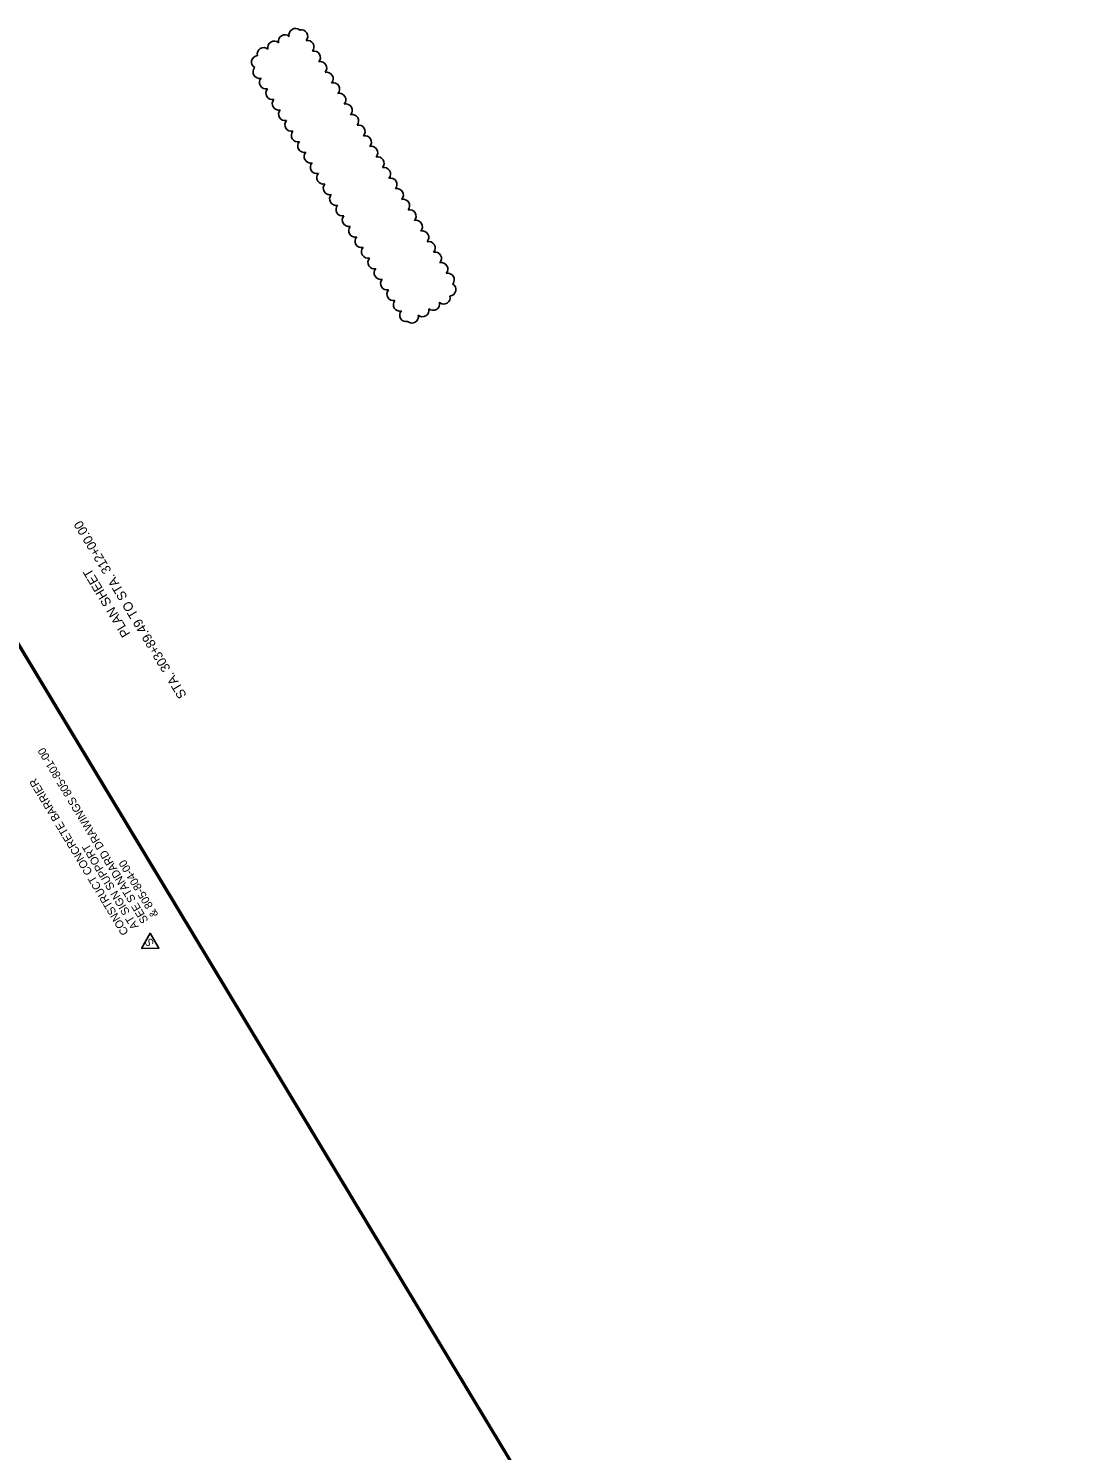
# Model space of a CAD drawing. Extents: x 1613170 to 1614989, y 1084261 to 1086549.
# Drawn here: x 1614158 to 1614953, y 1085483 to 1086549 of the extents above; entities that cross this region are included whole.
import ezdxf

# ---------------------------------------------------------------- set-up
doc = ezdxf.new("R2010")
doc.units = 0
for name, color, linetype in [('Level 17', 7, 'Continuous'), ('Level 21', 7, 'Continuous'), ('Level 4', 7, 'Continuous'), ('Level 8', 7, 'Continuous')]:
    doc.layers.add(name, color=color, linetype=linetype)

msp = doc.modelspace()

# ---------------------------------------------------------------- linework, layer by layer
at = {"layer": 'Level 17'}
msp.add_lwpolyline([(1614088.5, 1084350.8), (1613395.8, 1085500.1), (1613423.8, 1085516.9), (1613343.7, 1085653.3), (1614126.4, 1086125), (1614900.7, 1084840.3)], close=True, dxfattribs=at)
msp.add_lwpolyline([(1614088.5, 1084350.8), (1613395.8, 1085500.1), (1613423.8, 1085516.9), (1613343.7, 1085653.3), (1614126.4, 1086125), (1614900.7, 1084840.3)], close=True, dxfattribs=at)
msp.add_lwpolyline([(1614088.5, 1084350.8), (1613395.8, 1085500.1), (1613423.8, 1085516.9), (1613343.7, 1085653.3), (1614126.4, 1086125), (1614900.7, 1084840.3)], close=True, dxfattribs=at)
at = {"layer": 'Level 4'}
msp.add_lwpolyline([(1614134, 1084261.5), (1613269.4, 1085696.1), (1614088.6, 1086189.8), (1614953.2, 1084755.2)], close=True, dxfattribs=at)
at = {"layer": 'Level 8'}
msp.add_lwpolyline([(1614242.4, 1085859), (1614255.4, 1085859.3), (1614248.7, 1085870.4)], close=True, dxfattribs=at)
for centre, radius, start, end in [((1614349.8, 1086539.2), 4.86, 48.5768, 193.5768), ((1614357.7, 1086543.9), 4.86, 48.5768, 193.5768), ((1614362.1, 1086542.9), 4.86, 318.5768, 103.5768), ((1614333.9, 1086529.6), 4.86, 48.5768, 193.5768), ((1614341.8, 1086534.4), 4.86, 48.5768, 193.5768), ((1614366.8, 1086534.9), 4.86, 318.5768, 103.5768), ((1614371.6, 1086527), 4.86, 318.5768, 103.5768), ((1614329.6, 1086523.6), 4.85, 94.9006, 239.9006), ((1614376.4, 1086519.1), 4.86, 318.5768, 103.5768), ((1614330.8, 1086516.2), 4.86, 138.5768, 283.5768), ((1614335.6, 1086508.3), 4.86, 138.5768, 283.5768), ((1614381.2, 1086511.1), 4.86, 318.5768, 103.5768), ((1614340.4, 1086500.3), 4.86, 138.5768, 283.5768), ((1614386, 1086503.2), 4.86, 318.5768, 103.5768), ((1614390.7, 1086495.3), 4.86, 318.5768, 103.5768), ((1614345.2, 1086492.4), 4.86, 138.5768, 283.5768), ((1614349.9, 1086484.5), 4.86, 138.5768, 283.5768), ((1614395.5, 1086487.3), 4.86, 318.5768, 103.5768), ((1614354.7, 1086476.5), 4.86, 138.5768, 283.5768), ((1614400.3, 1086479.4), 4.86, 318.5768, 103.5768), ((1614359.5, 1086468.6), 4.86, 138.5768, 283.5768), ((1614405.1, 1086471.5), 4.86, 318.5768, 103.5768), ((1614409.9, 1086463.5), 4.86, 318.5768, 103.5768), ((1614364.3, 1086460.7), 4.86, 138.5768, 283.5768), ((1614369.1, 1086452.7), 4.86, 138.5768, 283.5768), ((1614414.6, 1086455.6), 4.86, 318.5768, 103.5768), ((1614373.8, 1086444.8), 4.86, 138.5768, 283.5768), ((1614419.4, 1086447.7), 4.86, 318.5768, 103.5768), ((1614378.6, 1086436.9), 4.86, 138.5768, 283.5768), ((1614424.2, 1086439.7), 4.86, 318.5768, 103.5768), ((1614429, 1086431.8), 4.86, 318.5768, 103.5768), ((1614383.4, 1086429), 4.86, 138.5768, 283.5768), ((1614388.2, 1086421), 4.86, 138.5768, 283.5768), ((1614433.8, 1086423.9), 4.86, 318.5768, 103.5768), ((1614393, 1086413.1), 4.86, 138.5768, 283.5768), ((1614438.5, 1086415.9), 4.86, 318.5768, 103.5768), ((1614397.7, 1086405.2), 4.86, 138.5768, 283.5768), ((1614443.3, 1086408), 4.86, 318.5768, 103.5768), ((1614448.1, 1086400.1), 4.86, 318.5768, 103.5768), ((1614402.5, 1086397.2), 4.86, 138.5768, 283.5768), ((1614407.3, 1086389.3), 4.86, 138.5768, 283.5768), ((1614452.9, 1086392.1), 4.86, 318.5768, 103.5768), ((1614412.1, 1086381.4), 4.86, 138.5768, 283.5768), ((1614457.7, 1086384.2), 4.86, 318.5768, 103.5768), ((1614462.4, 1086376.3), 4.86, 318.5768, 103.5768), ((1614416.9, 1086373.4), 4.86, 138.5768, 283.5768), ((1614467.2, 1086368.4), 4.86, 318.5768, 103.5768), ((1614421.6, 1086365.5), 4.86, 138.5768, 283.5768), ((1614426.4, 1086357.6), 4.86, 138.5768, 283.5768), ((1614472, 1086360.4), 4.86, 318.5768, 103.5768), ((1614431.2, 1086349.6), 4.86, 138.5768, 283.5768), ((1614473.2, 1086353), 4.85, 274.9006, 59.9006), ((1614436, 1086341.7), 4.86, 138.5768, 283.5768), ((1614453, 1086337.5), 4.86, 228.5768, 13.5768), ((1614461, 1086342.3), 4.86, 228.5768, 13.5768), ((1614468.9, 1086347), 4.86, 228.5768, 13.5768), ((1614440.8, 1086333.8), 4.86, 138.5768, 283.5768), ((1614445.1, 1086332.7), 4.86, 228.5768, 13.5768)]:
    msp.add_arc(centre, radius, start, end, dxfattribs=at)

# ---------------------------------------------------------------- texts
at = {"layer": 'Level 21'}
for s, height, p in [('STA. 303+89.49 TO STA. 312+00.00', 6.983, (1614276.4, 1086048.9)), ('PLAN SHEET', 6.98, (1614234.1, 1086094.9))]:
    msp.add_text(s, height=height, rotation=121.0768, dxfattribs=at).set_placement(p)
at = {"layer": 'Level 8'}
for s, p in [('SEE STANDARD DRAWINGS 805-801-00', (1614247.7, 1085880)), ('CONSTRUCT CONCRETE BARRIER ', (1614232.9, 1085871.1)), ('AT SIGN SUPPORT', (1614240.3, 1085875.5)), ('& 805-804-00', (1614255.1, 1085884.5)), ('S', (1614252.1, 1085862.7))]:
    msp.add_text(s, height=6, rotation=121.0768, dxfattribs=at).set_placement(p)

doc.saveas('drawing.dxf')
